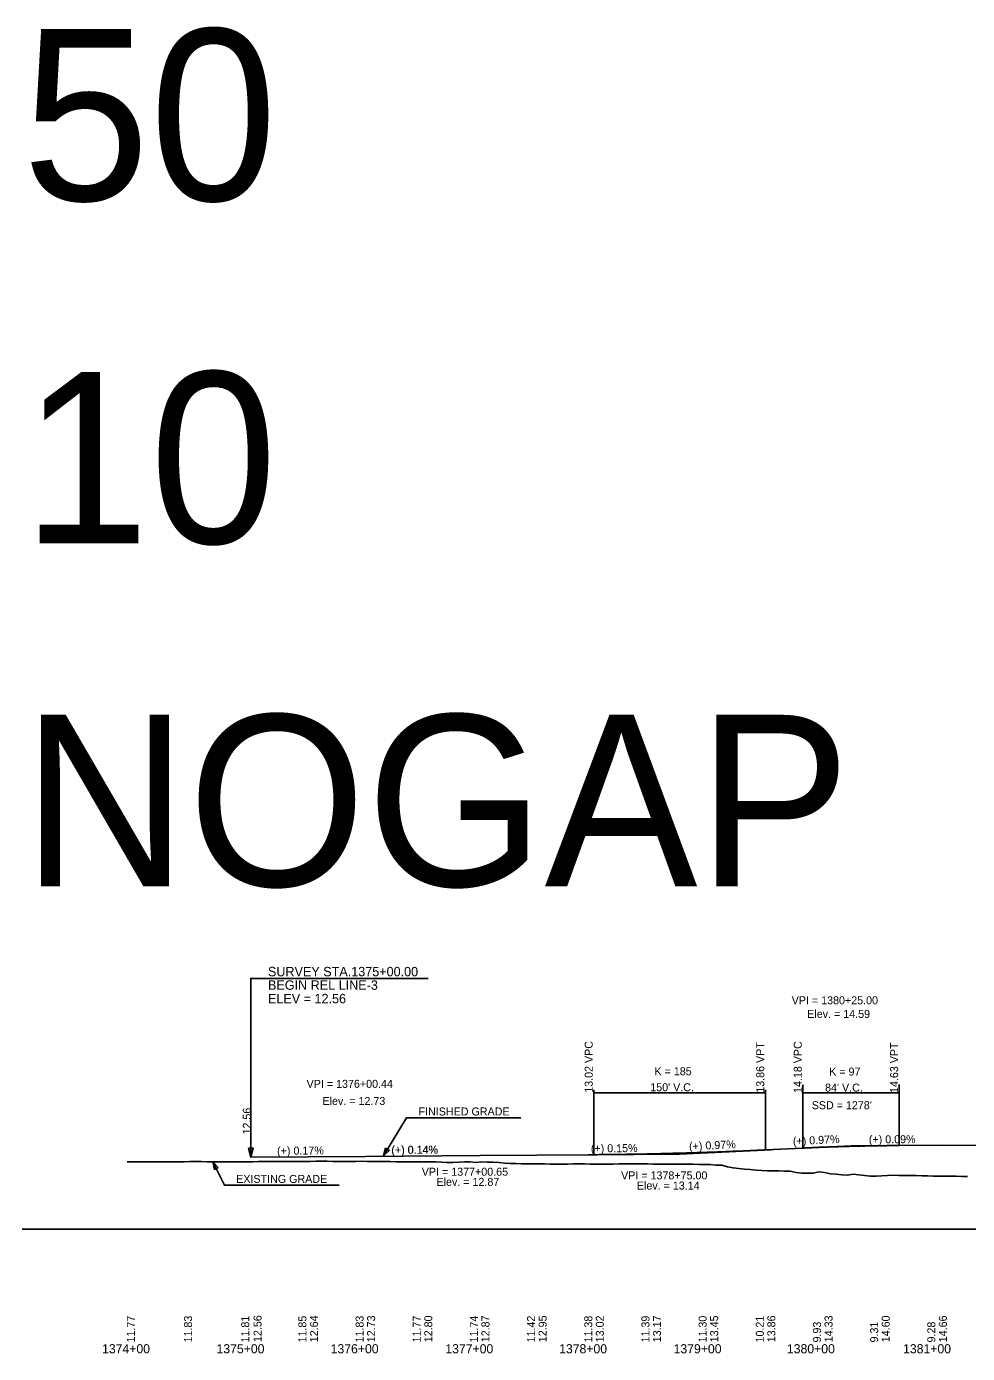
# Model space of a CAD drawing. Extents: x 2360994 to 2383826, y 330623 to 403123.
# Drawn here: x 2368829 to 2369652, y 351764 to 352925 of the extents above; entities that cross this region are included whole.
import ezdxf

# ---------------------------------------------------------------- set-up
doc = ezdxf.new("R2010")
doc.units = 0
for name, color, linetype in [('RD_DDB_GradeTX', 7, 'Continuous'), ('RD_DDB_Profile_EX', 7, 'Continuous'), ('RD_DDB_Profile_Lbl', 7, 'Continuous'), ('RD_DDB_Profile_PR', 7, 'Continuous'), ('RD_DDB_StaTX', 7, 'Continuous'), ('RD_DDB_StripGrade', 7, 'Continuous'), ('RD_DDB_VCLbl', 7, 'Continuous'), ('RD_GPK_Profile_Cell', 7, 'Continuous'), ('RD_TX_Profile', 7, 'Continuous')]:
    doc.layers.add(name, color=color, linetype=linetype)

msp = doc.modelspace()

# ---------------------------------------------------------------- linework, layer by layer
at = {"layer": 'RD_DDB_GradeTX'}
for p, q in [((2369470.7, 351942), (2369550.6, 351945.8)), ((2369630.6, 351946.2), (2369550.6, 351945.8)), ((2369320.6, 351938), (2369400.6, 351938.6)), ((2369480.5, 351942.4), (2369400.6, 351938.6))]:
    msp.add_line(p, q, dxfattribs=at)
at = {"layer": 'RD_DDB_Profile_EX'}
for points in [[(2368917.4, 351931.7), (2368922.4, 351931.8), (2368927.4, 351931.7), (2368932.4, 351931.7), (2368937.4, 351931.8), (2368942.4, 351931.8), (2368947.4, 351931.9), (2368952.4, 351931.9), (2368957.4, 351931.9), (2368962.4, 351931.9), (2368967.4, 351931.9), (2368972.4, 351932), (2368977.4, 351932), (2368982.4, 351932), (2368987.4, 351931.9), (2368992.4, 351931.9), (2368997.4, 351931.9), (2369002.4, 351931.9), (2369007.4, 351931.9), (2369012.4, 351931.9), (2369017.4, 351931.9), (2369022.4, 351931.9), (2369027.4, 351931.9), (2369032.4, 351932), (2369037.4, 351932), (2369042.4, 351932), (2369047.4, 351932), (2369052.4, 351932), (2369057.4, 351932), (2369062.4, 351932.1), (2369067.4, 351932.1), (2369072.4, 351932.1), (2369077.4, 351932.1), (2369082.4, 351932.2), (2369087.4, 351932.2), (2369092.4, 351932.2), (2369097.4, 351932.1), (2369102.4, 351932.1), (2369107.4, 351932.1), (2369112.4, 351932.1), (2369117.4, 351932.1), (2369122.4, 351932.2), (2369127.4, 351932), (2369132.4, 351932), (2369137.4, 351932), (2369142.4, 351932), (2369147.4, 351932), (2369152.4, 351931.9), (2369157.4, 351931.8), (2369162.4, 351931.8), (2369167.4, 351931.8), (2369172.4, 351931.7), (2369177.4, 351931.7), (2369182.4, 351931.7), (2369187.4, 351931.7), (2369192.4, 351931.4), (2369197.4, 351931.2), (2369202.4, 351931.2), (2369207.4, 351931.4), (2369212.4, 351931.8), (2369217.4, 351931.9), (2369222.4, 351931.3), (2369227.4, 351931.7), (2369232.4, 351931.5), (2369237.4, 351931.4), (2369242.4, 351931.1), (2369247.4, 351930.7), (2369252.4, 351930.4), (2369257.4, 351930.2), (2369262.4, 351930), (2369267.4, 351930), (2369272.4, 351930), (2369277.4, 351930), (2369282.4, 351929.9), (2369287.4, 351929.8), (2369292.4, 351929.8), (2369297.4, 351929.7), (2369302.4, 351929.8), (2369307.4, 351929.9), (2369312.4, 351930), (2369317.4, 351929.9), (2369322.4, 351929.8), (2369327.4, 351929.8), (2369332.4, 351929.8), (2369337.4, 351929.8), (2369342.4, 351929.8), (2369347.4, 351930.1), (2369352.4, 351930.1), (2369357.4, 351930.1), (2369362.4, 351930), (2369367.4, 351929.9), (2369372.4, 351929.9), (2369377.4, 351929.8), (2369382.4, 351929.7), (2369387.4, 351929.7), (2369392.4, 351929.6), (2369397.4, 351929.7), (2369402.4, 351929.7), (2369407.4, 351929.6), (2369412.4, 351929.6), (2369417.4, 351929.5)], [(2369417.4, 351929.5), (2369422.4, 351929.5), (2369427.4, 351929.3), (2369432.4, 351928.8), (2369437.4, 351928.8), (2369442.4, 351927.4), (2369447.4, 351926.4), (2369452.4, 351925.8), (2369457.4, 351925.4), (2369462.4, 351925), (2369467.4, 351924.4), (2369472.4, 351924.1), (2369477.4, 351923.9), (2369482.4, 351923.9), (2369487.4, 351923.8), (2369492.4, 351923.6), (2369497.4, 351923.5), (2369502.4, 351922.5), (2369507.4, 351921.9), (2369512.4, 351921.7), (2369517.4, 351921.8), (2369522.4, 351923), (2369527.4, 351922.3), (2369532.4, 351921.4), (2369537.4, 351921), (2369542.4, 351920.4), (2369547.4, 351920.1), (2369552.4, 351921.1), (2369557.4, 351920.4), (2369562.4, 351919.8), (2369567.4, 351919.1), (2369572.4, 351919.2), (2369577.4, 351919.6), (2369582.4, 351919.9), (2369587.4, 351920), (2369592.4, 351919.9), (2369597.4, 351919.8), (2369602.4, 351919.8), (2369607.4, 351919.7), (2369612.4, 351919.6), (2369617.4, 351919.4), (2369622.4, 351919.3), (2369627.4, 351919.2), (2369632.4, 351919.1), (2369637.4, 351919.2), (2369642.4, 351919.1), (2369647.4, 351919), (2369652.4, 351918.8)]]:
    msp.add_lwpolyline(points, dxfattribs=at)
at = {"layer": 'RD_DDB_Profile_PR'}
for p, q in [((2369475.6, 351942.2), (2369508.4, 351943.8)), ((2369592.7, 351946), (2369750.6, 351946.8)), ((2369025.6, 351935.7), (2369126, 351936.5)), ((2369126, 351936.5), (2369226.2, 351937.2)), ((2369226.2, 351937.2), (2369325.6, 351938))]:
    msp.add_line(p, q, dxfattribs=at)
for points in [[(2369508.4, 351943.8), (2369510.1, 351943.9), (2369511.8, 351944), (2369513.5, 351944), (2369515.2, 351944.1), (2369516.8, 351944.2), (2369518.5, 351944.3), (2369520.2, 351944.3), (2369521.9, 351944.4), (2369523.6, 351944.5), (2369525.3, 351944.5), (2369527, 351944.6), (2369528.6, 351944.7), (2369530.3, 351944.7), (2369532, 351944.8), (2369533.7, 351944.8), (2369535.4, 351944.9), (2369537.1, 351945), (2369538.8, 351945), (2369540.4, 351945.1), (2369542.1, 351945.1), (2369543.8, 351945.2), (2369545.5, 351945.2), (2369547.2, 351945.3), (2369548.9, 351945.3), (2369550.6, 351945.4), (2369552.3, 351945.4), (2369553.9, 351945.5), (2369555.6, 351945.5), (2369557.3, 351945.5), (2369559, 351945.6), (2369560.7, 351945.6), (2369562.4, 351945.6), (2369564.1, 351945.7), (2369565.7, 351945.7), (2369567.4, 351945.7), (2369569.1, 351945.8), (2369570.8, 351945.8), (2369572.5, 351945.8), (2369574.2, 351945.9), (2369575.9, 351945.9), (2369577.5, 351945.9), (2369579.2, 351945.9), (2369580.9, 351945.9), (2369582.6, 351946), (2369584.3, 351946), (2369586, 351946), (2369587.7, 351946), (2369589.3, 351946), (2369591, 351946), (2369592.7, 351946)], [(2369325.6, 351938), (2369328.6, 351938), (2369331.6, 351938.1), (2369334.6, 351938.1), (2369337.6, 351938.1), (2369340.6, 351938.1), (2369343.6, 351938.2), (2369346.6, 351938.2), (2369349.6, 351938.3), (2369352.6, 351938.3), (2369355.6, 351938.4), (2369358.6, 351938.4), (2369361.6, 351938.5), (2369364.6, 351938.5), (2369367.6, 351938.6), (2369370.6, 351938.6), (2369373.6, 351938.7), (2369376.6, 351938.7), (2369379.6, 351938.8), (2369382.6, 351938.9), (2369385.6, 351939), (2369388.6, 351939), (2369391.6, 351939.1), (2369394.6, 351939.2), (2369397.6, 351939.3), (2369400.6, 351939.3), (2369403.6, 351939.4), (2369406.6, 351939.5), (2369409.6, 351939.6), (2369412.6, 351939.7), (2369415.6, 351939.8), (2369418.6, 351939.9), (2369421.6, 351940), (2369424.6, 351940.1), (2369427.6, 351940.2), (2369430.6, 351940.3), (2369433.6, 351940.4), (2369436.6, 351940.5), (2369439.6, 351940.6), (2369442.6, 351940.8), (2369445.6, 351940.9), (2369448.6, 351941), (2369451.6, 351941.1), (2369454.6, 351941.2), (2369457.6, 351941.4), (2369460.6, 351941.5), (2369463.6, 351941.6), (2369466.6, 351941.8), (2369469.6, 351941.9), (2369472.6, 351942.1), (2369475.6, 351942.2)]]:
    msp.add_spline(points, degree=3, dxfattribs=at)
at = {"layer": 'RD_DDB_VCLbl'}
for p, q in [((2369325.6, 351994.7), (2369325.6, 351938)), ((2369325.6, 351992.2), (2369475.6, 351992.2)), ((2369475.6, 351994.7), (2369475.6, 351942.2)), ((2369508.4, 351999.1), (2369508.4, 351943.8)), ((2369508.4, 351992), (2369592.7, 351992)), ((2369592.7, 351999.5), (2369592.7, 351946))]:
    msp.add_line(p, q, dxfattribs=at)
at = {"layer": 'RD_GPK_Profile_Cell'}
msp.add_line((2368825.6, 351872.9), (2374525.6, 351872.9), dxfattribs=at)
at = {"layer": 'RD_TX_Profile'}
for p, q in [((2369180.7, 352092.3), (2369035.6, 352092.3)), ((2369261.8, 351970.3), (2369167.3, 351970.3)), ((2369102.9, 351911.3), (2369007.8, 351911.3))]:
    msp.add_line(p, q, dxfattribs=at)
for points in [[(2369035.6, 352092.3), (2369025.6, 352092.3), (2369025.6, 351935.7)], [(2369167.3, 351970.3), (2369161.8, 351970.3), (2369141.5, 351937)], [(2369007.8, 351911.3), (2369002.5, 351911.3), (2368992.4, 351931.9)]]:
    msp.add_lwpolyline(points, dxfattribs=at)
for points in [[(2369023.5, 351943.6), (2369025.6, 351935.7), (2369027.8, 351943.6)], [(2369143.5, 351943.7), (2369141.5, 351937), (2369146.6, 351941.8)], [(2368997, 351926.7), (2368992.4, 351931.9), (2368993.7, 351925.1)]]:
    msp.add_lwpolyline(points, close=True, dxfattribs=at)

# ---------------------------------------------------------------- texts
at = {"layer": 'RD_DDB_GradeTX'}
for s, rotation, p in [('(+) 0.97%', 2.7673, (2369499.8, 351946.3)), ('(+) 0.09%', 0.2691, (2369566.1, 351947.9)), ('(+) 0.17%', 0.4874, (2369048.6, 351937.9)), ('(+) 0.14%', 0.3981, (2369148.4, 351938.7)), ('(+) 0.14%', 0.3981, (2369148.6, 351938.7)), ('(+) 0.15%', 0.4431, (2369323, 351940)), ('(+) 0.97%', 2.7673, (2369409, 351941.8))]:
    msp.add_text(s, height=7, rotation=rotation, dxfattribs=at).set_placement(p)
at = {"layer": 'RD_DDB_Profile_Lbl'}
for s, p in [('VPI = 1380+25.00', (2369498.6, 352069.6)), ('Elev. = 14.59', (2369512.2, 352057.7)), ('VPI = 1376+00.44', (2369074.4, 351996.5)), ('Elev. = 12.73', (2369088.3, 351981.5)), ('VPI = 1377+00.65', (2369175.1, 351919.6)), ('VPI = 1378+75.00', (2369349.4, 351916.4)), ('Elev. = 12.87', (2369188, 351910.7)), ('Elev. = 13.14', (2369363.2, 351907.5))]:
    msp.add_text(s, height=7, dxfattribs=at).set_placement(p)
msp.add_text('12.56', height=7, rotation=90, dxfattribs=at).set_placement((2369025.6, 351955.7))
at = {"layer": 'RD_DDB_StaTX'}
for s, p in [('1374+00', (2368895.5, 351764.2)), ('1375+00', (2368995.6, 351764.2)), ('1376+00', (2369095.4, 351764.2)), ('1377+00', (2369195.7, 351764.2)), ('1378+00', (2369295.2, 351764.2)), ('1379+00', (2369395.3, 351764.2)), ('1380+00', (2369494.4, 351764.2)), ('1381+00', (2369596, 351764.2))]:
    msp.add_text(s, height=8, dxfattribs=at).set_placement(p)
at = {"layer": 'RD_DDB_StripGrade'}
for s, p in [('13.02 VPC', (2369324.6, 351992.2)), ('14.18 VPC', (2369507.4, 351992)), ('13.86 VPT', (2369474.6, 351992.2)), ('14.63 VPT', (2369591.7, 351992)), ('11.77', (2368924.2, 351773.7)), ('11.83', (2368974.2, 351773.7)), ('11.81', (2369024.2, 351773.7)), ('12.56', (2369035, 351774.1)), ('11.85', (2369074.2, 351773.7)), ('12.64', (2369084.3, 351773.9)), ('11.83', (2369124.2, 351773.7)), ('12.73', (2369134.3, 351773.9)), ('11.77', (2369174.2, 351773.7)), ('12.80', (2369184.3, 351773.9)), ('11.74', (2369224.2, 351773.7)), ('12.87', (2369234.3, 351773.9)), ('11.42', (2369274.2, 351773.7)), ('12.95', (2369284.3, 351773.9)), ('11.38', (2369324.2, 351773.7)), ('13.02', (2369334.3, 351773.9)), ('11.39', (2369374.2, 351773.7)), ('13.17', (2369384.3, 351773.9)), ('11.30', (2369424.2, 351773.7)), ('13.45', (2369434.3, 351773.9)), ('10.21', (2369474.2, 351773.7)), ('13.86', (2369484.3, 351773.9)), ('14.33', (2369534.3, 351773.9)), ('14.60', (2369584.3, 351773.9)), ('14.66', (2369634.3, 351773.9)), ('9.93', (2369524.2, 351773.7)), ('9.31', (2369574.2, 351773.7)), ('9.28', (2369624.2, 351773.7))]:
    msp.add_text(s, height=7, rotation=90, dxfattribs=at).set_placement(p)
at = {"layer": 'RD_DDB_VCLbl'}
for s, p in [('K = 185', (2369378.6, 352007.5)), ('K = 97', (2369531.4, 352007.2)), ("150' V.C.", (2369374.9, 351993.5)), ("84' V.C.", (2369527.8, 351993.2)), ("SSD = 1278'", (2369516.1, 351977.8))]:
    msp.add_text(s, height=7, dxfattribs=at).set_placement(p)
at = {"layer": 'RD_GPK_Profile_Cell'}
for s, p in [('50', (2368825.6, 352772.9)), ('10', (2368825.6, 352472.9)), ('NOGAP', (2368825.6, 352172.9))]:
    msp.add_text(s, height=150, dxfattribs=at).set_placement(p)
at = {"layer": 'RD_TX_Profile'}
for s, height, p in [('SURVEY STA.1375+00.00', 8.235, (2369040.6, 352094.1)), ('BEGIN REL LINE-3', 8.235, (2369040.6, 352082.3)), ('ELEV = 12.56', 8.235, (2369040.6, 352070.5)), ('FINISHED GRADE', 7, (2369172.3, 351972.3)), ('EXISTING GRADE', 7, (2369012.8, 351913.3))]:
    msp.add_text(s, height=height, dxfattribs=at).set_placement(p)

doc.saveas('drawing.dxf')
